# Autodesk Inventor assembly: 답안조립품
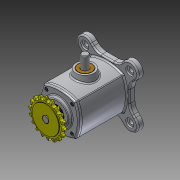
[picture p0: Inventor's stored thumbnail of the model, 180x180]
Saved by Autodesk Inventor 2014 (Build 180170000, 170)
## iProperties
Created: 2016-05
Part Number: 답안조립품
Document SubType Name: Assembly
Designer: Administrator
Author: Administrator
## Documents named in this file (11)
- C:\Users\Administrator\Desktop\460507V1013\답안조립품.iam
- C:\Users\Administrator\Desktop\460507V1013\본체.ipt
- C:\Users\Administrator\Desktop\460507V1013\M4x0.7x12.ipt
- C:\Users\Administrator\Desktop\460507V1013\베어링-6203.ipt
- C:\Users\Administrator\Desktop\460507V1013\부시.ipt
- C:\Users\Administrator\Desktop\460507V1013\스프로킷.ipt
- C:\Users\Administrator\Desktop\460507V1013\슬라이더.ipt
- C:\Users\Administrator\Desktop\460507V1013\오일실.ipt
- C:\Users\Administrator\Desktop\460507V1013\커버.ipt
- C:\Users\Administrator\Desktop\460507V1013\키5x5.ipt
- C:\Users\Administrator\Desktop\460507V1013\편심축.ipt
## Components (8 placed, 1 different names)
1. M4x0.7x12:1
2. M4x0.7x12:2
3. M4x0.7x12:3
4. M4x0.7x12:4
5. M4x0.7x12:5
6. M4x0.7x12:6
7. M4x0.7x12:7
8. M4x0.7x12:8
